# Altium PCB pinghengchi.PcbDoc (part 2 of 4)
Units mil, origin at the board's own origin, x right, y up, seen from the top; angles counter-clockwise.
Board outline 3880 x 3935 mil, 2 copper layers (Top Layer, Bottom Layer); 79 components, 147 nets, 520 pads, 52 vias.
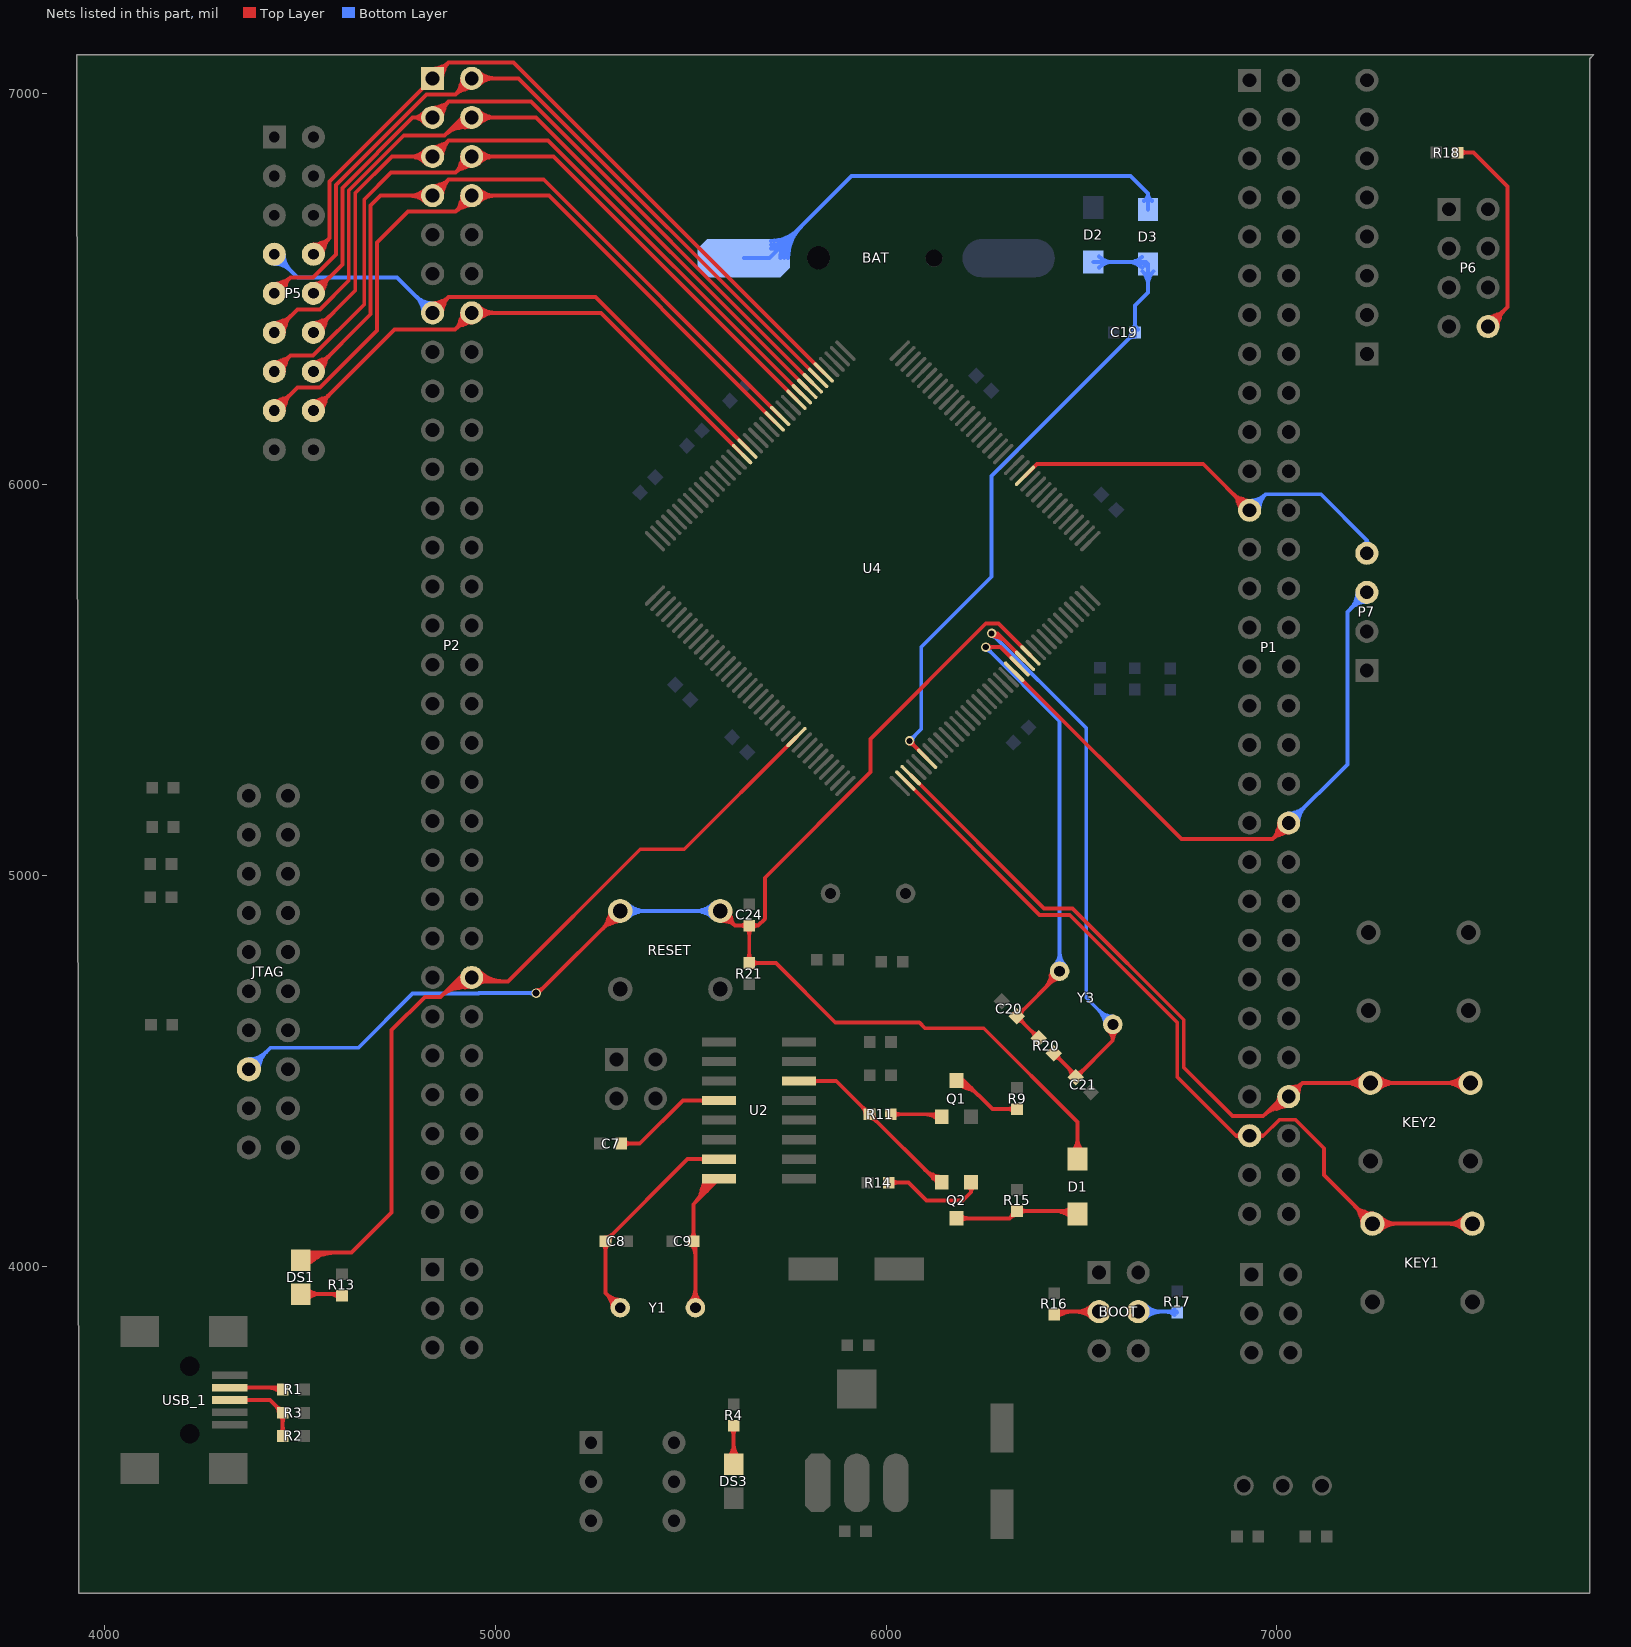
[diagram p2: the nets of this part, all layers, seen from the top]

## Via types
v1: diameter 24, hole 18, Top Layer to Bottom Layer, 42 vias
v2: diameter 24, hole 16, Top Layer to Bottom Layer, 4 vias
v3: diameter 125.98, hole 118.11, Top Layer to Bottom Layer, 4 vias
v4: diameter 30, hole 20, Top Layer to Bottom Layer, 2 vias

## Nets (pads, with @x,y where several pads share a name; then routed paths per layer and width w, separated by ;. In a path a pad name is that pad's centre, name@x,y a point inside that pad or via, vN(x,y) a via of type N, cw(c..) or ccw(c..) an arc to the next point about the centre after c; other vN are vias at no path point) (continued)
KEY1: KEY1.2 P1.55 U4.2 | length 3250.2
  Top Layer w10: U4.2@6049.15,5243.65 6392.81,4900 6470,4900 6745,4625 6745,4485 6895,4335 ; 7210.99,4136.5 ccw(c7251.76,4147.43) KEY1.2@7243.29,4106.08 ; 7217.59,4143.1 cw(c7206.67,4102.34) KEY1.2@7248.01,4110.8 ; KEY1.2@7500,4110 KEY1.2@7244.09,4110 7120,4234.09 7120,4303.02 7046.99,4376.03 7006.03,4376.03 6965,4335 ; 6895,4335 ccw(c6895,4347.71) 6906.94,4343.37 cw(c6895,4347.71) 6895,4335 ; 6895,4335 cw(c6895,4322.29) 6906.94,4326.63 ccw(c6895,4322.29) 6895,4335 ; 6895,4335 P1.55@6930,4335 6965,4335 ; 6965,4335 ccw(c6965,4322.29) 6953.06,4326.63 cw(c6965,4322.29) 6965,4335 ; 6965,4335 cw(c6965,4347.71) 6953.06,4343.37 ccw(c6965,4347.71) 6965,4335 ; 7199.71,4154.38 ccw(c7244.09,4198.77) 7244.09,4136 cw(c7244.09,4198.77) 7199.71,4154.38 ; 7199.71,4154.38 cw(c7155.32,4110) 7218.09,4110 ccw(c7155.32,4110) 7199.71,4154.38 ; 7216.78,4137.31 ccw(c7244.09,4164.63) 7244.09,4126 cw(c7244.09,4164.63) 7216.78,4137.31 ; 7216.78,4137.31 cw(c7189.47,4110) 7228.09,4110 ccw(c7189.47,4110) 7216.78,4137.31 ; 7282.72,4110 ccw(c7282.72,4071.37) 7255.41,4098.69 cw(c7282.72,4071.37) 7282.72,4110 ; 7282.72,4110 cw(c7282.72,4148.63) 7255.41,4121.31 ccw(c7282.72,4148.63) 7282.72,4110 ; 7306.86,4110 ccw(c7306.86,4047.23) 7262.48,4091.62 cw(c7306.86,4047.23) 7306.86,4110 ; 7306.86,4110 cw(c7306.86,4172.77) 7262.48,4128.38 ccw(c7306.86,4172.77) 7306.86,4110 ; 7437.23,4110 ccw(c7437.23,4172.77) 7481.62,4128.38 cw(c7437.23,4172.77) 7437.23,4110 ; 7437.23,4110 cw(c7437.23,4047.23) 7481.62,4091.62 ccw(c7437.23,4047.23) 7437.23,4110 ; 7461.37,4110 ccw(c7461.37,4148.63) 7488.69,4121.31 cw(c7461.37,4148.63) 7461.37,4110 ; 7461.37,4110 cw(c7461.37,4071.37) 7488.69,4098.69 ccw(c7461.37,4071.37) 7461.37,4110
KEY2: KEY2.2 P1.54 U4.3 | length 3539
  Top Layer w10: U4.3@6063.07,5257.57 6404.14,4916.5 6476.83,4916.5 6761.5,4631.83 6761.5,4510 6886.5,4385 6965,4385 ; 6999.06,4403.37 ccw(c6986.92,4454.87) P1.54@7034.97,4432.71 ; 7001.32,4419.49 cw(c7028.71,4412.15) P1.54@7030.31,4440.46 ; 7002.44,4414.09 ccw(c6995.17,4444.93) P1.54@7025.65,4436.24 ; P1.54@7017.76,4444.47 cw(c7052.2,4417.83) 7046.68,4461.01 ; P1.54@7039.47,4422.76 ccw(c7012.83,4457.2) 7056.01,4451.68 ; KEY2.2@7495,4470 KEY2.2@7239.09,4470 7065,4470 ; 6965,4385 cw(c7026.62,4323.39) 7029.26,4410.48 ccw(c7026.62,4323.39) 6965,4385 ; 6965,4385 7015,4435 P1.54@7030,4435 7065,4470 ; 7065,4470 ccw(c7091.64,4443.36) 7054.31,4438.3 cw(c7091.64,4443.36) 7065,4470 ; 7065,4470 cw(c7038.36,4496.64) 7033.3,4459.31 ccw(c7038.36,4496.64) 7065,4470 ; 7176.32,4470 ccw(c7176.32,4532.77) 7220.71,4488.38 cw(c7176.32,4532.77) 7176.32,4470 ; 7176.32,4470 cw(c7176.32,4407.23) 7220.71,4451.62 ccw(c7176.32,4407.23) 7176.32,4470 ; 7200.47,4470 ccw(c7200.47,4508.63) 7227.78,4481.31 cw(c7200.47,4508.63) 7200.47,4470 ; 7200.47,4470 cw(c7200.47,4431.37) 7227.78,4458.69 ccw(c7200.47,4431.37) 7200.47,4470 ; 7277.72,4470 ccw(c7277.72,4431.37) 7250.41,4458.69 cw(c7277.72,4431.37) 7277.72,4470 ; 7277.72,4470 cw(c7277.72,4508.63) 7250.41,4481.31 ccw(c7277.72,4508.63) 7277.72,4470 ; 7301.86,4470 ccw(c7301.86,4407.23) 7257.48,4451.62 cw(c7301.86,4407.23) 7301.86,4470 ; 7301.86,4470 cw(c7301.86,4532.77) 7257.48,4488.38 ccw(c7301.86,4532.77) 7301.86,4470 ; 7432.23,4470 ccw(c7432.23,4532.77) 7476.62,4488.38 cw(c7432.23,4532.77) 7432.23,4470 ; 7432.23,4470 cw(c7432.23,4407.23) 7476.62,4451.62 ccw(c7432.23,4407.23) 7432.23,4470 ; 7456.37,4470 ccw(c7456.37,4508.63) 7483.69,4481.31 cw(c7456.37,4508.63) 7456.37,4470 ; 7456.37,4470 cw(c7456.37,4431.37) 7483.69,4458.69 ccw(c7456.37,4431.37) 7456.37,4470 ; 6981.37,4401.37 cw(c7027.58,4355.16) 7029.56,4420.48 ccw(c7027.58,4355.16) 6981.37,4401.37 ; 6997.73,4417.73 cw(c7028.54,4386.92) 7029.86,4430.47 ccw(c7028.54,4386.92) 6997.73,4417.73 ; 6998.74,4418.74 ccw(c6982.47,4435) 7005.47,4435 cw(c6982.47,4435) 6998.74,4418.74
LED1: DS1.2 P2.48 U4.135 | length 3717.7
  Top Layer w10: DS1.2@4503.06,4017.04 4522.02,4036 4632,4036 4735,4139 4735,4605 4820,4690 4860,4690 ; DS1.2@4510.16,4026.64 ccw(c4521.8,4038.18) 4529.99,4023.99 ; DS1.2@4511.45,4025.04 ccw(c4527.96,4035.74) 4538.59,4019.19 ; DS1.2@4515.71,4035.1 ccw(c4522.66,4043.62) 4528.17,4034.09 ccw(c4533.67,4024.56) DS1.2@4522.81,4022.8 ; DS1.2@4517.26,4033.68 ccw(c4531.33,4047.64) 4541.23,4030.48 ; DS1.2@4519.85,4030.48 ccw(c4536.39,4041.2) 4547.04,4024.62 ; DS1.2@4522.38,4014.42 cw(c4537.17,4010.46) 4529.51,4023.72 ; 4530.14,4013.76 cw(c4519.53,4030.28) DS1.2@4503.06,4019.6 ; 4897.27,4720.54 ccw(c4890.01,4778.94) P2.48@4936.43,4742.78 ; 4899.28,4711.06 ccw(c4890.92,4778.22) P2.48@4944.32,4736.64 ; 4908.28,4731.65 ccw(c4905.46,4754.35) P2.48@4926.58,4745.57 ; 4923.23,4714.04 ccw(c4917.86,4757.24) P2.48@4952.21,4730.49 ; U4.135@5770.77,5355.01 5483.76,5068 5371.23,5068 5033.23,4730 4950,4730 P2.48@4940,4740 4910,4740 ; DS1.2@4503.06,4019.6 cw(c4542.66,3980) 4542.66,4036 ccw(c4542.66,3980) DS1.2@4503.06,4019.6 ; 4860,4690 cw(c4924.14,4625.86) 4936.62,4715.71 ccw(c4924.14,4625.86) 4860,4690 ; 4860,4690 4910,4740 ; 4910,4740 ccw(c4910,4746.08) 4915.96,4744.87 cw(c4910,4746.08) 4910,4740 ; 4910,4740 cw(c4910,4733.92) 4915.96,4735.13 ccw(c4910,4733.92) 4910,4740 ; 4975.07,4730 ccw(c4975.07,4704.93) 4957.34,4722.66 cw(c4975.07,4704.93) 4975.07,4730 ; 4975.07,4730 cw(c4975.07,4775.07) 4943.2,4743.2 ccw(c4975.07,4775.07) 4975.07,4730 ; DS1.2@4510.14,4012.53 cw(c4566.8,3955.86) 4566.8,4036 ccw(c4566.8,3955.86) DS1.2@4510.14,4012.53 ; DS1.2@4517.21,4005.46 cw(c4590.94,3931.72) 4590.94,4036 ccw(c4590.94,3931.72) DS1.2@4517.21,4005.46 ; 4874.21,4704.21 cw(c4927.61,4650.82) 4938,4725.61 ccw(c4927.61,4650.82) 4874.21,4704.21 ; 4888.42,4718.42 cw(c4931.07,4675.77) 4939.38,4735.52 ccw(c4931.07,4675.77) 4888.42,4718.42 ; 4902.63,4732.63 cw(c4934.54,4700.72) 4940.75,4745.42 ccw(c4934.54,4700.72) 4902.63,4732.63 ; P2.48@4950.27,4750.27 ccw(c4999.21,4799.21) 4999.21,4730 cw(c4999.21,4799.21) P2.48@4950.27,4750.27 ; P2.48@4957.34,4757.34 ccw(c5023.36,4823.36) 5023.36,4730 cw(c5023.36,4823.36) P2.48@4957.34,4757.34
NERST: C24.2 D1.1 JTAG.15 R21.1 RESET.1 U4.25 | length 6203.5
  Top Layer w10: v1(5105,4700) 5110,4700 RESET.1@5320,4910 ; 5286.9,4883.5 cw(c5327.66,4872.57) RESET.1@5319.2,4913.92 ; 5293.5,4876.9 ccw(c5282.57,4917.66) RESET.1@5323.92,4909.2 ; RESET.1@5560.91,4900.83 RESET.1@5560.91,4920 ; RESET.1@5564.51,4901.86 ccw(c5604.68,4930.55) 5598.02,4881.64 ; RESET.1@5575.91,4910 5613.41,4872.5 ; RESET.1@5584.04,4921.39 cw(c5555.36,4881.22) 5604.27,4887.89 ; U4.25@6369.3,5563.8 6288.1,5645 6255,5645 5960,5350 5960,5265 5690,4995 5690,4890 5672.5,4872.5 ; D1.1@6475,4290 D1.1@6490,4275 6490,4370 6250,4610 6100,4610 6085,4625 5870,4625 5718,4777 R21.1@5650,4777 5649.94,4777.06 C24.2@5649.94,4872.5 ; 5275.62,4865.62 ccw(c5231.23,4910) 5294,4910 cw(c5231.23,4910) 5275.62,4865.62 ; 5275.62,4865.62 cw(c5320,4821.23) 5320,4884 ccw(c5320,4821.23) 5275.62,4865.62 ; 5292.69,4882.69 ccw(c5265.37,4910) 5304,4910 cw(c5265.37,4910) 5292.69,4882.69 ; 5292.69,4882.69 cw(c5320,4855.37) 5320,4894 ccw(c5320,4855.37) 5292.69,4882.69 ; 5598.98,4886.92 ccw(c5581.11,4869.05) 5577.92,4894.13 cw(c5581.11,4869.05) 5598.98,4886.92 ; 5598.98,4886.92 cw(c5616.86,4904.8) 5591.78,4907.98 ccw(c5616.86,4904.8) 5598.98,4886.92 ; 5613.4,4872.5 ccw(c5584.36,4843.45) 5579.18,4884.21 cw(c5584.36,4843.45) 5613.4,4872.5 ; 5613.4,4872.5 cw(c5642.45,4901.55) 5601.7,4906.73 ccw(c5642.45,4901.55) 5613.4,4872.5 ; 5613.41,4872.5 C24.2@5649.94,4872.5 ; 5625.79,4872.5 ccw(c5625.79,4896.64) 5642.86,4879.57 cw(c5625.79,4896.64) 5625.79,4872.5 ; 5625.79,4872.5 cw(c5625.79,4848.36) C24.2@5642.86,4865.43 ; 5625.79,4872.5 cw(c5625.79,4848.36) C24.2@5642.86,4865.43 ; C24.2@5642.86,4865.43 cw(c5625.79,4848.36) 5649.94,4848.36 ; C24.2@5642.86,4865.43 cw(c5625.79,4848.36) 5649.94,4848.36 ; 5649.94,4848.36 cw(c5674.08,4848.36) 5657.01,4865.43 ccw(c5674.08,4848.36) 5649.94,4848.36 ; C24.2@5649.94,4872.5 5672.5,4872.5 ; R21.1@5657.07,4784.07 cw(c5674.3,4801.3) 5649.94,4801.3 ccw(c5674.3,4801.3) R21.1@5657.07,4784.07 ; R21.1@5657.07,4784.07 ccw(c5674.14,4801.14) 5674.14,4777 ; R21.1@5657.07,4784.07 ccw(c5674.14,4801.14) 5674.14,4777 ; 5672.5,4872.5 ccw(c5672.5,4852.05) 5657.34,4865.78 cw(c5672.5,4852.05) 5672.5,4872.5 ; 5672.5,4872.5 cw(c5672.5,4892.95) 5657.34,4879.22 ccw(c5672.5,4892.95) 5672.5,4872.5 ; 5674.14,4777 ccw(c5674.14,4752.86) 5657.07,4769.93 cw(c5674.14,4752.86) 5674.14,4777 ; 6490,4328.65 ccw(c6539.71,4328.65) 6504.56,4293.5 cw(c6539.71,4328.65) 6490,4328.65 ; 6490,4328.65 cw(c6440.29,4328.65) 6475.44,4293.5 ccw(c6440.29,4328.65) 6490,4328.65 ; v1@5105,4707 ccw(c5105,4735.97) 5125.49,4715.49 cw(c5105,4735.97) v1@5105,4707 ; R21.1@5642.93,4784.07 ccw(c5626.01,4800.99) 5649.94,4800.99 cw(c5626.01,4800.99) R21.1@5642.93,4784.07
  Bottom Layer w10: JTAG.15@4370,4505 4425,4560 4650,4560 4788.97,4698.97 4956.99,4698.97 4958.02,4700 v1(5105,4700) ; RESET.1@5320,4910 RESET.1@5575.91,4910 ; 4397.31,4532.31 ccw(c4424.63,4505) 4386,4505 cw(c4424.63,4505) 4397.31,4532.31 ; 4397.31,4532.31 cw(c4370,4559.63) 4370,4521 ccw(c4370,4559.63) 4397.31,4532.31 ; 4414.38,4549.38 ccw(c4458.77,4505) 4396,4505 cw(c4458.77,4505) 4414.38,4549.38 ; 4414.38,4549.38 cw(c4370,4593.77) 4370,4531 ccw(c4370,4593.77) 4414.38,4549.38 ; 5088.1,4700 ccw(c5088.1,4716.9) 5100.05,4704.95 cw(c5088.1,4716.9) 5088.1,4700 ; 5088.1,4700 cw(c5088.1,4683.1) 5100.05,4695.05 ccw(c5088.1,4683.1) 5088.1,4700 ; 5358.63,4910 ccw(c5358.63,4871.37) 5331.31,4898.69 cw(c5358.63,4871.37) 5358.63,4910 ; 5358.63,4910 cw(c5358.63,4948.63) 5331.31,4921.31 ccw(c5358.63,4948.63) 5358.63,4910 ; 5382.77,4910 ccw(c5382.77,4847.23) 5338.38,4891.62 cw(c5382.77,4847.23) 5382.77,4910 ; 5382.77,4910 cw(c5382.77,4972.77) 5338.38,4928.38 ccw(c5382.77,4972.77) 5382.77,4910 ; 5513.14,4910 ccw(c5513.14,4972.77) 5557.52,4928.38 cw(c5513.14,4972.77) 5513.14,4910 ; 5513.14,4910 cw(c5513.14,4847.23) 5557.52,4891.62 ccw(c5513.14,4847.23) 5513.14,4910 ; 5537.28,4910 ccw(c5537.28,4948.63) 5564.59,4921.31 cw(c5537.28,4948.63) 5537.28,4910 ; 5537.28,4910 cw(c5537.28,4871.37) 5564.59,4898.69 ccw(c5537.28,4871.37) 5537.28,4910
NetBAT_1: BAT.1 D3.1 | length 2046.1
  Bottom Layer w10: BAT.1@5636.35,6580 5702,6580 5912,6790 6625,6790 6670,6745 ; D3.1@6670,6705 6670,6745 ; 6670,6745 ccw(c6691.28,6745) 6680.47,6726.67 cw(c6691.28,6745) 6670,6745 ; 6670,6745 cw(c6648.72,6745) 6659.53,6726.67 ccw(c6648.72,6745) 6670,6745 ; BAT.1@5705.25,6604.21 ccw(c5705.25,6654.82) 5741.03,6619.03 cw(c5705.25,6654.82) BAT.1@5705.25,6604.21 ; BAT.1@5705.25,6614.21 ccw(c5705.25,6688.96) 5758.11,6636.11 cw(c5705.25,6688.96) BAT.1@5705.25,6614.21 ; BAT.1@5705.25,6624.21 ccw(c5705.25,6723.1) 5775.18,6653.18 cw(c5705.25,6723.1) BAT.1@5705.25,6624.21 ; BAT.1@5729.46,6580 cw(c5795.77,6580) 5748.88,6626.88 ccw(c5795.77,6580) BAT.1@5729.46,6580 ; BAT.1@5739.46,6580 cw(c5829.91,6580) 5765.96,6643.96 ccw(c5829.91,6580) BAT.1@5739.46,6580 ; BAT.1@5749.46,6580 cw(c5864.05,6580) 5783.03,6661.03 ccw(c5864.05,6580) BAT.1@5749.46,6580
NetBOOT_3: BOOT.3 R16.2 | length 551.3
  Top Layer w10: R16.2@6437.78,3883.71 ccw(c6447.97,3891.78) 6454.48,3880.52 ; BOOT.3@6545,3885 6437.44,3885 R16.2@6429.94,3877.5 ; R16.2@6429.94,3877.5 cw(c6448.04,3859.39) 6448.04,3885 ccw(c6448.04,3859.39) R16.2@6429.94,3877.5 ; 6485.79,3885 ccw(c6485.79,3944.21) 6527.66,3902.34 cw(c6485.79,3944.21) 6485.79,3885 ; 6485.79,3885 cw(c6485.79,3825.79) 6527.66,3867.66 ccw(c6485.79,3825.79) 6485.79,3885 ; 6509.93,3885 ccw(c6509.93,3920.07) 6534.73,3895.27 cw(c6509.93,3920.07) 6509.93,3885 ; 6509.93,3885 cw(c6509.93,3849.93) 6534.73,3874.73 ccw(c6509.93,3849.93) 6509.93,3885 ; R16.2@6437.01,3870.43 cw(c6472.18,3835.25) 6472.18,3885 ccw(c6472.18,3835.25) R16.2@6437.01,3870.43
NetBOOT_4: BOOT.4 R17.1 | length 472.9
  Bottom Layer w10: BOOT.4@6645,3885 6743,3885 R17.1@6745,3883 ; 6680.07,3885 ccw(c6680.07,3849.93) 6655.27,3874.73 cw(c6680.07,3849.93) 6680.07,3885 ; 6680.07,3885 cw(c6680.07,3920.07) 6655.27,3895.27 ccw(c6680.07,3920.07) 6680.07,3885 ; 6704.21,3885 ccw(c6704.21,3825.79) 6662.34,3867.66 cw(c6704.21,3825.79) 6704.21,3885 ; 6704.21,3885 cw(c6704.21,3944.21) 6662.34,3902.34 ccw(c6704.21,3944.21) 6704.21,3885 ; 6716.03,3885 cw(c6716.03,3854.03) 6737.93,3875.93 ccw(c6716.03,3854.03) 6716.03,3885 ; 6725.69,3885 ccw(c6725.69,3902.31) 6737.93,3890.07 cw(c6725.69,3902.31) 6725.69,3885
NetC7_2: C7.2 U2.4 | length 423.2
  Top Layer w10: C7.2@5322.5,4314.94 5369.94,4314.94 5480,4425 U2.4@5572.64,4425 ; 5346.64,4314.94 ccw(c5346.64,4290.79) 5329.57,4307.86 cw(c5346.64,4290.79) 5346.64,4314.94 ; 5346.64,4314.94 cw(c5346.64,4339.08) 5329.57,4322.01 ccw(c5346.64,4339.08) 5346.64,4314.94 ; 5524.7,4425 ccw(c5524.7,4441.44) 5536.33,4429.82 cw(c5524.7,4441.44) 5524.7,4425 ; 5524.7,4425 cw(c5524.7,4408.56) 5536.33,4420.18 ccw(c5524.7,4408.56) 5524.7,4425
NetC8_2: C8.2 U2.7 Y1.1 | length 995.1
  Top Layer w10: 5293.25,3920.2 ccw(c5327.01,3929.24) Y1.1@5320,3895 ; 5294.8,3921.75 cw(c5285.76,3887.99) Y1.1@5320,3895 ; U2.7@5572.64,4275 5492.44,4275 C8.2@5282.5,4065.06 5282.5,3932.5 Y1.1@5320,3895 ; 5282.5,4040.92 ccw(c5258.36,4040.92) 5275.43,4057.99 cw(c5258.36,4040.92) 5282.5,4040.92 ; 5282.5,4040.92 cw(c5306.64,4040.92) 5289.57,4057.99 ccw(c5306.64,4040.92) 5282.5,4040.92 ; 5285.86,3929.14 ccw(c5320,3963.28) 5320,3915 cw(c5320,3963.28) 5285.86,3929.14 ; 5285.86,3929.14 cw(c5251.72,3895) 5300,3895 ccw(c5251.72,3895) 5285.86,3929.14 ; 5299.57,4082.14 ccw(c5316.64,4065.06) 5292.5,4065.06 cw(c5316.64,4065.06) 5299.57,4082.14 ; 5299.57,4082.14 cw(c5282.5,4099.21) 5282.5,4075.06 ccw(c5282.5,4099.21) 5299.57,4082.14 ; 5524.7,4275 ccw(c5524.7,4291.44) 5536.33,4279.82 cw(c5524.7,4291.44) 5524.7,4275 ; 5524.7,4275 cw(c5524.7,4258.56) 5536.33,4270.18 ccw(c5524.7,4258.56) 5524.7,4275
NetC9_2: C9.2 U2.8 Y1.2 | length 1053.6
  Top Layer w10: Y1.2@5512.13,3895 5512.13,4060.31 C9.2@5507.5,4064.94 5507.5,4159.86 ; 5527.39,4194.87 cw(c5565.48,4186.09) U2.8@5544.75,4219.23 ; U2.8@5535.26,4221.57 cw(c5511.96,4208.01) 5538.03,4201.13 ; U2.8@5572.64,4225 5507.5,4159.86 ; 5507.5,4089.08 ccw(c5531.64,4089.08) 5514.57,4072.01 cw(c5531.64,4089.08) 5507.5,4089.08 ; 5507.5,4089.08 cw(c5483.36,4089.08) 5500.43,4072.01 ccw(c5483.36,4089.08) 5507.5,4089.08 ; 5507.5,4159.86 ccw(c5442.73,4224.64) 5534.33,4224.97 cw(c5442.73,4224.64) 5507.5,4159.86 ; 5512.13,3943.28 ccw(c5560.41,3943.28) 5526.27,3909.14 cw(c5560.41,3943.28) 5512.13,3943.28 ; 5512.13,3943.28 cw(c5463.84,3943.28) 5497.98,3909.14 ccw(c5463.84,3943.28) 5512.13,3943.28 ; C9.2@5500.43,4057.86 cw(c5472.19,4029.63) 5512.13,4029.63 ccw(c5472.19,4029.63) C9.2@5500.43,4057.86 ; 5524.48,4176.85 ccw(c5476.57,4224.76) 5544.33,4225.01 cw(c5476.57,4224.76) 5524.48,4176.85 ; 5541.47,4193.83 ccw(c5510.41,4224.89) 5554.33,4225.05 cw(c5510.41,4224.89) 5541.47,4193.83 ; 5558.45,4210.81 ccw(c5544.25,4225.01) 5564.33,4225.09 cw(c5544.25,4225.01) 5558.45,4210.81
NetC19_1: C19.1 D2.2 D3.2 U4.6 | length 2451.2
  Top Layer w10: v2(6060,5345) 6104.83,5300.17 U4.6@6104.83,5299.33 ; 6071.95,5333.05 ccw(c6060,5321.1) 6060,5338 cw(c6060,5321.1) 6071.95,5333.05 ; 6071.95,5333.05 cw(c6083.9,5345) 6067,5345 ccw(c6083.9,5345) 6071.95,5333.05
  Bottom Layer w10: v2(6060,5345) 6090,5375 6090,5585 6270,5765 6270,6023 C19.1@6637,6390 6637,6459 6670,6492 D3.2@6670,6565 6665,6570 D2.2@6530,6570 ; 6071.95,5356.95 ccw(c6083.9,5345) 6067,5345 cw(c6083.9,5345) 6071.95,5356.95 ; 6071.95,5356.95 cw(c6060,5368.9) 6060,5352 ccw(c6060,5368.9) 6071.95,5356.95 ; 6579.71,6570 ccw(c6579.71,6520.29) 6544.56,6555.44 cw(c6579.71,6520.29) 6579.71,6570 ; 6579.71,6570 cw(c6579.71,6619.71) 6544.56,6584.56 ccw(c6579.71,6619.71) 6579.71,6570 ; 6619.93,6372.93 ccw(c6602.86,6390) 6627,6390 cw(c6602.86,6390) 6619.93,6372.93 ; 6619.93,6372.93 cw(c6637,6355.86) 6637,6380 ccw(c6637,6355.86) 6619.93,6372.93 ; 6637,6414.14 ccw(c6661.14,6414.14) 6644.07,6397.07 cw(c6661.14,6414.14) 6637,6414.14 ; 6637,6414.14 cw(c6612.86,6414.14) 6629.93,6397.07 ccw(c6612.86,6414.14) 6637,6414.14 ; 6670,6511.35 ccw(c6620.29,6511.35) 6655.44,6546.5 cw(c6620.29,6511.35) 6670,6511.35 ; 6670,6511.35 cw(c6719.71,6511.35) 6684.56,6546.5 ccw(c6719.71,6511.35) 6670,6511.35 ; 6617.72,6570 cw(c6617.72,6516.66) 6655.44,6554.38 ccw(c6617.72,6516.66) 6617.72,6570 ; 6622.86,6570 ccw(c6622.86,6616.08) 6655.44,6583.5 cw(c6622.86,6616.08) 6622.86,6570 ; 6641.87,6570 cw(c6641.87,6540.8) 6662.51,6561.45 ccw(c6641.87,6540.8) 6641.87,6570
NetC20_2: C20.2 R20.2 U4.23 Y3.2 | length 2174.5
  Top Layer w10: v2(6255,5585) 6292.42,5585 U4.23@6341.46,5535.96 ; 6347,4627.13 cw(c6351.52,4644.02) C20.2@6334.4,4640.51 ; 6347,4653.89 ccw(c6351.52,4637) C20.2@6334.4,4640.51 ; 6347.78,4627.91 ccw(c6330.89,4623.39) C20.2@6334.4,4640.51 ; 6347.78,4653.11 cw(c6330.89,4657.63) C20.2@6334.4,4640.51 ; 6377.25,4596.98 ccw(c6393.96,4601.46) R20.2@6390.6,4584.49 ; 6377.89,4597.9 cw(c6373.32,4580.84) R20.2@6390.6,4584.49 ; 6416.51,4727.34 cw(c6455.94,4716.77) Y3.2@6444.15,4755.85 ; 6421.15,4744.69 cw(c6449.83,4737) Y3.2@6441.26,4765.43 ; 6422.27,4729.99 ccw(c6414.58,4758.68) Y3.2@6444.15,4755.85 ; 6271.9,5585 ccw(c6271.9,5568.1) 6259.95,5580.05 cw(c6271.9,5568.1) 6271.9,5585 ; 6271.9,5585 cw(c6271.9,5601.9) 6259.95,5589.95 ccw(c6271.9,5601.9) 6271.9,5585 ; C20.2@6334.4,4640.51 6390.42,4584.49 R20.2@6390.6,4584.49 ; C20.2@6334.4,4640.51 6444.15,4750.26 Y3.2@6444.15,4755.85 ; C20.2@6344.4,4640.51 ccw(c6368.54,4640.51) 6351.47,4623.44 ; C20.2@6344.4,4640.51 cw(c6368.54,4640.51) 6351.47,4657.58 ; C20.2@6344.4,4640.51 ccw(c6368.54,4640.51) 6351.47,4623.44 ; C20.2@6344.4,4640.51 cw(c6368.54,4640.51) 6351.47,4657.58 ; 6351.47,4623.44 ccw(c6334.4,4606.37) 6334.4,4630.51 cw(c6334.4,4606.37) 6351.47,4623.44 ; 6351.47,4657.58 cw(c6334.4,4674.65) 6334.4,4650.51 ccw(c6334.4,4674.65) 6351.47,4657.58 ; 6373.22,4601.69 ccw(c6390.6,4619.07) 6390.6,4594.49 cw(c6390.6,4619.07) 6373.22,4601.69 ; 6373.66,4601.25 cw(c6356.89,4584.49) 6380.6,4584.49 ccw(c6356.89,4584.49) 6373.66,4601.25 ; 6406.05,4712.15 ccw(c6362.35,4755.85) 6424.15,4755.85 cw(c6362.35,4755.85) 6406.05,4712.15 ; 6419.56,4725.67 cw(c6444.15,4701.08) 6444.15,4735.85 ccw(c6444.15,4701.08) 6419.56,4725.67 ; 6423.12,4729.23 ccw(c6396.49,4755.85) 6434.15,4755.85 cw(c6396.49,4755.85) 6423.12,4729.23
  Bottom Layer w10: v2(6255,5585) 6444.15,5395.85 Y3.2@6444.15,4755.85 ; 6266.95,5573.05 ccw(c6255,5561.1) 6255,5578 cw(c6255,5561.1) 6266.95,5573.05 ; 6266.95,5573.05 cw(c6278.9,5585) 6262,5585 ccw(c6278.9,5585) 6266.95,5573.05 ; 6444.15,4804.14 ccw(c6492.43,4804.14) 6458.29,4770 cw(c6492.43,4804.14) 6444.15,4804.14 ; 6444.15,4804.14 cw(c6395.86,4804.14) 6430,4770 ccw(c6395.86,4804.14) 6444.15,4804.14
NetC21_2: C21.2 R20.1 U4.24 Y3.1 | length 2297.7
  Top Layer w10: v2@6276.06,5623.5 ccw(c6310.69,5643.49) 6300.34,5604.87 ; 6285.26,5620 U4.24@6355.38,5549.88 ; 6441.69,4532.53 cw(c6446.21,4549.41) R20.1@6429.09,4545.91 ; 6442.47,4533.31 ccw(c6425.59,4528.79) R20.1@6429.09,4545.91 ; 6471.44,4500 ccw(c6493.49,4505.91) C21.2@6485.6,4484.49 ; 6498.2,4497.87 ccw(c6502.72,4480.98) C21.2@6485.6,4484.49 ; 6498.98,4497.09 cw(c6482.09,4501.61) C21.2@6485.6,4484.49 ; Y3.1@6580,4620 6580,4578.89 ; R20.1@6429.09,4545.91 6485.6,4489.4 C21.2@6485.6,4484.49 ; 6446.16,4528.84 ccw(c6429.09,4511.77) 6429.09,4535.91 cw(c6429.09,4511.77) 6446.16,4528.84 ; 6446.16,4528.84 cw(c6463.23,4545.91) 6439.09,4545.91 ccw(c6463.23,4545.91) 6446.16,4528.84 ; C21.2@6485.6,4484.49 6580,4578.89 ; C21.2@6485.6,4494.49 ccw(c6485.6,4518.63) 6502.67,4501.56 ; C21.2@6485.6,4494.49 cw(c6485.6,4506.78) 6476.91,4498.09 ccw(c6485.6,4506.78) C21.2@6485.6,4494.49 ; C21.2@6485.6,4494.49 ccw(c6485.6,4518.63) 6502.67,4501.56 ; 6502.67,4501.56 ccw(c6519.74,4484.49) 6495.6,4484.49 cw(c6519.74,4484.49) 6502.67,4501.56 ; 6580,4578.89 ccw(c6547.76,4578.89) 6567.66,4604.26 cw(c6547.76,4578.89) 6580,4578.89 ; 6580,4578.89 cw(c6612.24,4578.89) 6592.34,4604.26 ccw(c6612.24,4578.89) 6580,4578.89 ; v2@6270,5613 cw(c6270,5559.26) 6308,5597.26 ccw(c6270,5559.26) v2@6270,5613 ; v2@6270,5623 cw(c6270,5593.4) 6290.93,5614.33 ccw(c6270,5593.4) v2@6270,5623 ; 6465.06,4509.94 cw(c6439.61,4484.49) 6475.6,4484.49 ccw(c6439.61,4484.49) 6465.06,4509.94
  Bottom Layer w10: v2(6270,5620) 6512,5378 6512,4688 Y3.1@6580,4620 ; 6281.95,5608.05 ccw(c6270,5596.1) 6270,5613 cw(c6270,5596.1) 6281.95,5608.05 ; 6281.95,5608.05 cw(c6293.9,5620) 6277,5620 ccw(c6293.9,5620) 6281.95,5608.05 ; 6545.86,4654.14 ccw(c6580,4688.28) 6580,4640 cw(c6580,4688.28) 6545.86,4654.14 ; 6545.86,4654.14 cw(c6511.72,4620) 6560,4620 ccw(c6511.72,4620) 6545.86,4654.14
NetD1_2: D1.2 Q2.3 R15.2 | length 784.5
  Top Layer w10: Q2.3@6180,4123.74 6316.18,4123.74 R15.2@6334.94,4142.5 6482.5,4142.5 D1.2@6490,4135 ; 6210.7,4123.74 ccw(c6210.7,4093.04) 6188.99,4114.75 cw(c6210.7,4093.04) 6210.7,4123.74 ; 6210.7,4123.74 cw(c6210.7,4154.44) 6188.99,4132.73 ccw(c6210.7,4154.44) 6210.7,4123.74 ; 6317.86,4125.43 ccw(c6300.79,4142.5) 6324.94,4142.5 cw(c6300.79,4142.5) 6317.86,4125.43 ; 6317.86,4125.43 cw(c6334.94,4108.36) 6334.94,4132.5 ccw(c6334.94,4108.36) 6317.86,4125.43 ; 6359.08,4142.5 ccw(c6359.08,4118.36) 6342.01,4135.43 cw(c6359.08,4118.36) 6359.08,4142.5 ; 6359.08,4142.5 cw(c6359.08,4166.64) 6342.01,4149.57 ccw(c6359.08,4166.64) 6359.08,4142.5 ; 6431.69,4142.5 cw(c6431.69,4080.63) 6475.44,4124.38 ccw(c6431.69,4080.63) 6431.69,4142.5 ; 6448.89,4142.5 ccw(c6448.89,4180.05) 6475.44,4153.5 cw(c6448.89,4180.05) 6448.89,4142.5 ; 6455.83,4142.5 cw(c6455.83,4104.77) 6482.51,4131.45 ccw(c6455.83,4104.77) 6455.83,4142.5
NetDS1_1: DS1.1 R13.1 | length 317.8
  Top Layer w10: DS1.1@4503.06,3930.03 4603.97,3930.03 R13.1@4608,3926 ; 4551.35,3930.03 ccw(c4551.35,3881.75) 4517.21,3915.89 cw(c4551.35,3881.75) 4551.35,3930.03 ; 4551.35,3930.03 cw(c4551.35,3978.32) 4517.21,3944.17 ccw(c4551.35,3978.32) 4551.35,3930.03 ; 4574.12,3930.03 cw(c4574.12,3892.12) 4600.93,3918.93 ccw(c4574.12,3892.12) 4574.12,3930.03
NetDS3_1: DS3.1 R4.1 | length 325.6
  Top Layer w10: DS3.1@5609.94,3494.97 5610,3495.03 R4.1@5610,3593 ; 5610,3568.86 ccw(c5585.86,3568.86) 5602.93,3585.93 cw(c5585.86,3568.86) 5610,3568.86 ; 5610,3568.86 cw(c5634.14,3568.86) 5617.07,3585.93 ccw(c5634.14,3568.86) 5610,3568.86 ; DS3.1@5595.79,3511.67 ccw(c5561.5,3545.97) 5610,3545.97 cw(c5561.5,3545.97) DS3.1@5595.79,3511.67 ; 5610,3545.66 ccw(c5658.07,3545.66) 5624.08,3511.67 cw(c5658.07,3545.66) 5610,3545.66
NetP6_8: P6.8 R18.1 | length 999.9
  Top Layer w10: R18.1@7462,6850 7503,6850 7590,6763 7590,6455 P6.8@7540,6405 ; P6.8@7534.64,6406.1 cw(c7572.3,6398.39) 7562.35,6435.52 ; P6.8@7541.1,6399.64 ccw(c7533.39,6437.3) 7570.52,6427.35 ; 7486.14,6850 ccw(c7486.14,6825.86) 7469.07,6842.93 cw(c7486.14,6825.86) 7486.14,6850 ; 7486.14,6850 cw(c7486.14,6874.14) 7469.07,6857.07 ccw(c7486.14,6874.14) 7486.14,6850 ; 7564.8,6429.8 ccw(c7589.6,6405) 7554.53,6405 cw(c7589.6,6405) 7564.8,6429.8 ; 7564.8,6429.8 cw(c7540,6454.6) 7540,6419.53 ccw(c7540,6454.6) 7564.8,6429.8 ; 7581.87,6446.87 ccw(c7623.74,6405) 7564.53,6405 cw(c7623.74,6405) 7581.87,6446.87 ; 7581.87,6446.87 cw(c7540,6488.74) 7540,6429.53 ccw(c7540,6488.74) 7581.87,6446.87
NetQ1_2: Q1.2 R11.1 | length 344.1
  Top Layer w10: R11.1@6012,4390 6136.34,4390 Q1.2@6142.6,4383.74 ; 6036.14,4390 ccw(c6036.14,4365.86) 6019.07,4382.93 cw(c6036.14,4365.86) 6036.14,4390 ; 6036.14,4390 cw(c6036.14,4414.14) 6019.07,4397.07 ccw(c6036.14,4414.14) 6036.14,4390 ; 6099.16,4390 cw(c6099.16,4341.29) 6133.61,4375.73 ccw(c6099.16,4341.29) 6099.16,4390 ; 6123.3,4390 cw(c6123.3,4365.43) 6140.68,4382.8 ccw(c6123.3,4365.43) 6123.3,4390 ; 6124.63,4390 ccw(c6124.63,4402.69) 6133.61,4393.72 cw(c6124.63,4402.69) 6124.63,4390
NetQ1_3: Q1.3 R9.1 | length 634
  Top Layer w10: Q1.3@6180,4476.26 6198.74,4476.26 ; Q1.3@6182.35,4476.63 ccw(c6224.35,4500.88) 6211.8,4454.04 ; Q1.3@6186.36,4464.26 cw(c6197.23,4445.43) 6202.86,4466.43 ; Q1.3@6191.48,4480.75 ccw(c6219.52,4494.14) 6211.48,4464.12 ; R9.1@6335,4403 6272,4403 6198.74,4476.26 ; 6198.74,4476.26 ccw(c6198.74,4468.81) 6191.82,4471.56 cw(c6198.74,4468.81) 6198.74,4476.26 ; 6198.74,4476.26 cw(c6198.74,4483.71) 6191.82,4480.96 ccw(c6198.74,4483.71) 6198.74,4476.26 ; 6310.86,4403 ccw(c6310.86,4427.14) 6327.93,4410.07 cw(c6310.86,4427.14) 6310.86,4403 ; 6310.86,4403 cw(c6310.86,4378.86) 6327.93,4395.93 ccw(c6310.86,4378.86) 6310.86,4403 ; Q1.3@6180,4462.56 cw(c6180,4384.24) 6235.38,4439.62 ccw(c6180,4384.24) Q1.3@6180,4462.56 ; Q1.3@6180,4472.56 cw(c6180,4418.38) 6218.31,4456.69 ccw(c6180,4418.38) Q1.3@6180,4472.56 ; Q1.3@6180,4482.56 cw(c6180,4452.52) 6201.24,4473.76 ccw(c6180,4452.52) Q1.3@6180,4482.56
NetQ2_1: Q2.1 R11.2 U2.14 | length 895.1
  Top Layer w10: U2.14@5777.36,4475 5872.56,4475 R11.2@5957.5,4390.06 6131.3,4216.26 Q2.1@6142.6,4216.26 ; 6113.44,4237.77 cw(c6102.53,4197.06) Q2.1@6140.17,4216.02 ; Q2.1@6130.07,4215.08 ccw(c6116.56,4212.75) 6120.11,4225.99 ccw(c6125.5,4246.11) Q2.1@6136.12,4228.19 ; 5825.3,4475 ccw(c5825.3,4458.56) 5813.67,4470.18 cw(c5825.3,4458.56) 5825.3,4475 ; 5825.3,4475 cw(c5825.3,4491.44) 5813.67,4479.82 ccw(c5825.3,4491.44) 5825.3,4475 ; 5940.43,4407.14 ccw(c5957.5,4424.21) 5957.5,4400.06 cw(c5957.5,4424.21) 5940.43,4407.14 ; 5940.43,4407.14 cw(c5923.36,4390.06) 5947.5,4390.06 ccw(c5923.36,4390.06) 5940.43,4407.14 ; 5974.57,4372.99 ccw(c5957.5,4355.92) 5957.5,4380.06 cw(c5957.5,4355.92) 5974.57,4372.99 ; 5974.57,4372.99 cw(c5991.64,4390.06) 5967.5,4390.06 ccw(c5991.64,4390.06) 5974.57,4372.99 ; 6099.93,4247.64 ccw(c6142.6,4290.3) 6142.6,4229.96 cw(c6142.6,4290.3) 6099.93,4247.64 ; 6117,4230.56 ccw(c6142.6,4256.16) 6142.6,4219.96 cw(c6142.6,4256.16) 6117,4230.56
NetQ2_2: Q2.2 R14.1 | length 408
  Top Layer w10: R14.1@6007,4215 6057,4215 6103,4169 6196,4169 6217.4,4190.4 ; Q2.2@6217.4,4216.26 6217.4,4190.4 ; 6031.14,4215 ccw(c6031.14,4190.86) 6014.07,4207.93 cw(c6031.14,4190.86) 6031.14,4215 ; 6031.14,4215 cw(c6031.14,4239.14) 6014.07,4222.07 ccw(c6031.14,4239.14) 6031.14,4215 ; 6217.4,4190.4 ccw(c6199.44,4190.4) 6209.96,4204.97 cw(c6199.44,4190.4) 6217.4,4190.4 ; 6217.4,4190.4 cw(c6235.37,4190.4) 6224.85,4204.97 ccw(c6235.37,4190.4) 6217.4,4190.4
NetR1_2: R1.2 USB_1.2 | length 229.4
  Top Layer w10: USB_1.2@4321.06,3690.5 R1.2@4452.07,3690.5 ; 4368.18,3690.5 ccw(c4368.18,3678.81) 4359.91,3687.07 cw(c4368.18,3678.81) 4368.18,3690.5 ; 4368.18,3690.5 cw(c4368.18,3702.19) 4359.91,3693.92 ccw(c4368.18,3702.19) 4368.18,3690.5 ; 4421.65,3690.5 cw(c4421.65,3651.22) 4449.43,3678.99 ccw(c4421.65,3651.22) 4421.65,3690.5
NetR2_2: R2.2 R3.2 USB_1.3 | length 472.3
  Top Layer w10: USB_1.3@4321.06,3659 4423.56,3659 R3.2@4456.5,3626.06 R2.2@4456.5,3567.06 ; 4368.18,3659 ccw(c4368.18,3647.31) 4359.91,3655.58 cw(c4368.18,3647.31) 4368.18,3659 ; 4368.18,3659 cw(c4368.18,3670.69) 4359.91,3662.43 ccw(c4368.18,3670.69) 4368.18,3659 ; 4439.43,3643.14 ccw(c4456.5,3660.21) 4456.5,3636.06 cw(c4456.5,3660.21) 4439.43,3643.14 ; 4439.43,3643.14 cw(c4422.36,3626.06) 4446.5,3626.06 ccw(c4422.36,3626.06) 4439.43,3643.14 ; 4456.5,3591.21 ccw(c4480.64,3591.21) 4463.57,3574.14 cw(c4480.64,3591.21) 4456.5,3591.21 ; 4456.5,3591.21 cw(c4432.36,3591.21) 4449.43,3574.14 ccw(c4432.36,3591.21) 4456.5,3591.21 ; 4456.5,3601.92 ccw(c4432.36,3601.92) 4449.43,3618.99 cw(c4432.36,3601.92) 4456.5,3601.92 ; 4456.5,3601.92 cw(c4480.64,3601.92) 4463.57,3618.99 ccw(c4480.64,3601.92) 4456.5,3601.92
OLED_SCL: P1.40 P7.3 U4.22 | length 2534.9
  Top Layer w10: U4.22@6327.54,5522.04 6755.61,5093.97 6988.97,5093.97 ; 6999.68,5111.69 cw(c7037.8,5102.07) P1.40@7028.74,5140.33 ; 7006.69,5104.68 ccw(c6997.07,5142.8) P1.40@7035.33,5133.74 ; P1.40@7030,5135 6988.97,5093.97 ; 6988.97,5093.97 ccw(c6949.13,5133.82) 7005.48,5134.64 cw(c6949.13,5133.82) 6988.97,5093.97 ; 6988.97,5093.97 cw(c7028.82,5054.13) 7029.64,5110.48 ccw(c7028.82,5054.13) 6988.97,5093.97 ; 7005.7,5110.7 ccw(c6982.1,5134.3) 7015.47,5134.79 cw(c6982.1,5134.3) 7005.7,5110.7 ; 7005.7,5110.7 cw(c7029.3,5087.1) 7029.79,5120.47 ccw(c7029.3,5087.1) 7005.7,5110.7
  Bottom Layer w10: P1.40@7030,5135 7180,5285 7180,5675 P7.3@7230,5725 ; 7054.8,5159.8 ccw(c7079.6,5135) 7044.53,5135 cw(c7079.6,5135) 7054.8,5159.8 ; 7054.8,5159.8 cw(c7030,5184.6) 7030,5149.53 ccw(c7030,5184.6) 7054.8,5159.8 ; 7071.87,5176.87 ccw(c7113.74,5135) 7054.53,5135 cw(c7113.74,5135) 7071.87,5176.87 ; 7071.87,5176.87 cw(c7030,5218.74) 7030,5159.53 ccw(c7030,5218.74) 7071.87,5176.87 ; 7188.13,5683.13 ccw(c7146.26,5725) 7205.47,5725 cw(c7146.26,5725) 7188.13,5683.13 ; 7188.13,5683.13 cw(c7230,5641.26) 7230,5700.47 ccw(c7230,5641.26) 7188.13,5683.13 ; 7205.2,5700.2 ccw(c7180.4,5725) 7215.47,5725 cw(c7180.4,5725) 7205.2,5700.2 ; 7205.2,5700.2 cw(c7230,5675.4) 7230,5710.47 ccw(c7230,5675.4) 7205.2,5700.2
OLED_SDA: P1.23 P7.4 U4.49 | length 1756
  Top Layer w10: U4.49@6355.38,6023.14 6385.83,6053.58 6811.42,6053.58 P1.23@6930,5935 ; 6899.48,5957.35 ccw(c6936.61,5967.3) P1.23@6928.9,5929.64 ; 6907.65,5965.52 cw(c6897.7,5928.39) P1.23@6935.36,5936.1 ; 6888.13,5976.87 ccw(c6930,6018.74) 6930,5959.53 cw(c6930,6018.74) 6888.13,5976.87 ; 6888.13,5976.87 cw(c6846.26,5935) 6905.47,5935 ccw(c6846.26,5935) 6888.13,5976.87 ; 6905.2,5959.8 ccw(c6930,5984.6) 6930,5949.53 cw(c6930,5984.6) 6905.2,5959.8 ; 6905.2,5959.8 cw(c6880.4,5935) 6915.47,5935 ccw(c6880.4,5935) 6905.2,5959.8
  Bottom Layer w10: P1.23@6930,5935 6971.03,5976.03 ; P7.4@7230,5825 7230,5858.23 ; 6954.3,5959.3 ccw(c6977.9,5935.7) 6944.53,5935.21 cw(c6977.9,5935.7) 6954.3,5959.3 ; 6954.3,5959.3 cw(c6930.7,5982.9) 6930.21,5949.53 ccw(c6930.7,5982.9) 6954.3,5959.3 ; 6971.03,5976.03 ccw(c7010.87,5936.18) 6954.52,5935.36 cw(c7010.87,5936.18) 6971.03,5976.03 ; 6971.03,5976.03 cw(c6931.18,6015.87) 6930.36,5959.52 ccw(c6931.18,6015.87) 6971.03,5976.03 ; 6971.03,5976.03 7112.21,5976.03 7230,5858.23 ; 7230,5858.23 ccw(c7240.25,5858.23) 7237.23,5848.44 cw(c7240.25,5858.23) 7230,5858.23 ; 7230,5858.23 cw(c7219.75,5858.23) 7222.77,5848.44 ccw(c7219.75,5858.23) 7230,5858.23
OV_D0: P2.1 P5.8 U4.77 | length 2668.2
  Top Layer w10: P5.8@4529.67,6591.26 cw(c4567.93,6582.2) 4558.31,6620.32 ; P5.8@4535,6590 4576.03,6631.03 ; P5.8@4536.26,6584.67 ccw(c4527.2,6622.93) 4565.32,6613.31 ; P2.1@4834.67,7041.26 cw(c4872.93,7032.2) 4863.31,7070.32 ; P2.1@4841.26,7034.67 ccw(c4832.2,7072.93) 4870.32,7063.31 ; U4.77@5840.36,6287.61 5046.94,7081.03 4881.03,7081.03 ; 4559.3,6614.3 ccw(c4582.9,6590.7) 4549.53,6590.21 cw(c4582.9,6590.7) 4559.3,6614.3 ; 4559.3,6614.3 cw(c4535.7,6637.9) 4535.21,6604.53 ccw(c4535.7,6637.9) 4559.3,6614.3 ; 4576.03,6631.03 ccw(c4615.87,6591.18) 4559.52,6590.36 cw(c4615.87,6591.18) 4576.03,6631.03 ; 4576.03,6631.03 cw(c4536.18,6670.87) 4535.36,6614.52 ccw(c4536.18,6670.87) 4576.03,6631.03 ; 4576.03,6631.03 4576.03,6776.03 P2.1@4840,7040 4881.03,7081.03 ; P2.1@4864.3,7064.3 ccw(c4887.9,7040.7) 4854.53,7040.21 cw(c4887.9,7040.7) P2.1@4864.3,7064.3 ; P2.1@4864.3,7064.3 cw(c4840.7,7087.9) 4840.21,7054.53 ccw(c4840.7,7087.9) P2.1@4864.3,7064.3 ; 4881.03,7081.03 ccw(c4920.87,7041.18) 4864.52,7040.36 cw(c4920.87,7041.18) 4881.03,7081.03 ; 4881.03,7081.03 cw(c4841.18,7120.87) 4840.36,7064.52 ccw(c4841.18,7120.87) 4881.03,7081.03
OV_D1: P2.2 P5.9 U4.78 | length 3083
  Top Layer w10: P5.9@4429.67,6491.26 cw(c4467.93,6482.2) 4458.31,6520.32 ; P5.9@4435,6490 4476.03,6531.03 ; P5.9@4436.26,6484.67 ccw(c4427.2,6522.93) 4465.32,6513.31 ; 4909.68,7016.69 cw(c4947.8,7007.07) P2.2@4938.74,7045.33 ; 4916.69,7009.68 ccw(c4907.07,7047.8) P2.2@4945.33,7038.74 ; U4.78@5826.44,6273.69 5060.13,7040 P2.2@4940,7040 4898.97,6998.97 ; 4459.3,6514.3 ccw(c4482.9,6490.7) 4449.53,6490.21 cw(c4482.9,6490.7) 4459.3,6514.3 ; 4459.3,6514.3 cw(c4435.7,6537.9) 4435.21,6504.53 ccw(c4435.7,6537.9) 4459.3,6514.3 ; 4476.03,6531.03 ccw(c4515.87,6491.18) 4459.52,6490.36 cw(c4515.87,6491.18) 4476.03,6531.03 ; 4476.03,6531.03 cw(c4436.18,6570.87) 4435.36,6514.52 ccw(c4436.18,6570.87) 4476.03,6531.03 ; 4476.03,6531.03 4534.05,6531.03 4592.53,6589.51 4592.53,6767.53 4823.97,6998.97 4898.97,6998.97 ; 4898.97,6998.97 ccw(c4859.13,7038.82) 4915.48,7039.64 cw(c4859.13,7038.82) 4898.97,6998.97 ; 4898.97,6998.97 cw(c4938.82,6959.13) 4939.64,7015.48 ccw(c4938.82,6959.13) 4898.97,6998.97 ; 4915.7,7015.7 ccw(c4892.1,7039.3) 4925.47,7039.79 cw(c4892.1,7039.3) 4915.7,7015.7 ; 4915.7,7015.7 cw(c4939.3,6992.1) 4939.79,7025.47 ccw(c4939.3,6992.1) 4915.7,7015.7 ; 4975.07,7040 ccw(c4975.07,7004.93) 4950.27,7029.73 cw(c4975.07,7004.93) 4975.07,7040 ; 4975.07,7040 cw(c4975.07,7075.07) 4950.27,7050.27 ccw(c4975.07,7075.07) 4975.07,7040 ; 4999.21,7040 ccw(c4999.21,6980.79) 4957.34,7022.66 cw(c4999.21,6980.79) 4999.21,7040 ; 4999.21,7040 cw(c4999.21,7099.21) 4957.34,7057.34 ccw(c4999.21,7099.21) 4999.21,7040
OV_D2: P2.3 P5.10 U4.79 | length 2881.2
  Top Layer w10: P5.10@4529.64,6491.1 cw(c4567.3,6483.39) 4557.35,6520.52 ; P5.10@4535,6490 4609.03,6564.03 4609.03,6760 4789.03,6940 ; P5.10@4536.1,6484.64 ccw(c4528.39,6522.3) 4565.52,6512.35 ; P2.3@4834.67,6941.26 cw(c4872.93,6932.2) 4863.31,6970.32 ; P2.3@4841.26,6934.67 ccw(c4832.2,6972.93) 4870.32,6963.31 ; U4.79@5812.52,6259.77 5091.26,6981.03 4881.03,6981.03 ; 4559.8,6514.8 ccw(c4584.6,6490) 4549.53,6490 cw(c4584.6,6490) 4559.8,6514.8 ; 4559.8,6514.8 cw(c4535,6539.6) 4535,6504.53 ccw(c4535,6539.6) 4559.8,6514.8 ; 4576.87,6531.87 ccw(c4618.74,6490) 4559.53,6490 cw(c4618.74,6490) 4576.87,6531.87 ; 4576.87,6531.87 cw(c4535,6573.74) 4535,6514.53 ccw(c4535,6573.74) 4576.87,6531.87 ; 4789.03,6940 ccw(c4789.03,6980.7) 4820.83,6955.3 cw(c4789.03,6980.7) 4789.03,6940 ; 4789.03,6940 cw(c4789.03,6899.3) 4820.83,6924.7 ccw(c4789.03,6899.3) 4789.03,6940 ; 4789.03,6940 P2.3@4840,6940 4881.03,6981.03 ; 4809.81,6940 ccw(c4809.81,6964.1) 4828.65,6949.06 cw(c4809.81,6964.1) 4809.81,6940 ; 4809.81,6940 cw(c4809.81,6915.9) 4828.65,6930.94 ccw(c4809.81,6915.9) 4809.81,6940 ; 4864.3,6964.3 ccw(c4887.9,6940.7) 4854.53,6940.21 cw(c4887.9,6940.7) 4864.3,6964.3 ; 4864.3,6964.3 cw(c4840.7,6987.9) 4840.21,6954.53 ccw(c4840.7,6987.9) 4864.3,6964.3 ; 4881.03,6981.03 ccw(c4920.87,6941.18) 4864.52,6940.36 cw(c4920.87,6941.18) 4881.03,6981.03 ; 4881.03,6981.03 cw(c4841.18,7020.87) 4840.36,6964.52 ccw(c4841.18,7020.87) 4881.03,6981.03
OV_D3: P2.4 P5.11 U4.80 | length 3128.5
  Top Layer w10: P5.11@4429.64,6391.1 cw(c4467.3,6383.39) 4457.35,6420.52 ; P5.11@4435,6390 4493.97,6448.97 4551.99,6448.97 4625.53,6522.51 4625.53,6753.17 4766.18,6893.82 4870.48,6893.82 ; P5.11@4436.1,6384.64 ccw(c4428.39,6422.3) 4465.52,6412.35 ; 4899.09,6911.32 ccw(c4891.16,6978.53) P2.4@4944.3,6936.61 ; 4923.07,6914.15 ccw(c4917.97,6957.38) P2.4@4952.15,6930.42 ; U4.80@5798.6,6245.85 5104.45,6940 P2.4@4940,6940 4916.67,6940 4870.48,6893.82 ; 4459.8,6414.8 ccw(c4484.6,6390) 4449.53,6390 cw(c4484.6,6390) 4459.8,6414.8 ; 4459.8,6414.8 cw(c4435,6439.6) 4435,6404.53 ccw(c4435,6439.6) 4459.8,6414.8 ; 4476.87,6431.87 ccw(c4518.74,6390) 4459.53,6390 cw(c4518.74,6390) 4476.87,6431.87 ; 4476.87,6431.87 cw(c4435,6473.74) 4435,6414.53 ccw(c4435,6473.74) 4476.87,6431.87 ; 4870.49,6893.82 cw(c4925.32,6838.99) 4936.47,6915.73 ccw(c4925.32,6838.99) 4870.49,6893.82 ; 4975.07,6940 ccw(c4975.07,6904.93) 4950.27,6929.73 cw(c4975.07,6904.93) 4975.07,6940 ; 4975.07,6940 cw(c4975.07,6975.07) 4950.27,6950.27 ccw(c4975.07,6975.07) 4975.07,6940 ; 4999.21,6940 ccw(c4999.21,6880.79) 4957.34,6922.66 cw(c4999.21,6880.79) 4999.21,6940 ; 4999.21,6940 cw(c4999.21,6999.21) 4957.34,6957.34 ccw(c4999.21,6999.21) 4999.21,6940 ; 4884.59,6907.92 cw(c4928.9,6863.61) 4937.91,6925.62 ccw(c4928.9,6863.61) 4884.59,6907.92 ; 4898.69,6922.02 cw(c4932.48,6888.23) 4939.35,6935.52 ccw(c4932.48,6888.23) 4898.69,6922.02
OV_D4: P2.5 P5.12 U4.81 | length 2918.4
  Top Layer w10: P5.12@4529.64,6391.1 cw(c4567.3,6383.39) 4557.35,6420.52 ; P5.12@4535,6390 4642.03,6497.03 4642.03,6746.33 4735.7,6840 P2.5@4840,6840 4881.03,6881.03 ; P5.12@4536.1,6384.64 ccw(c4528.39,6422.3) 4565.52,6412.35 ; P2.5@4834.67,6841.26 cw(c4872.93,6832.2) 4863.31,6870.32 ; P2.5@4841.26,6834.67 ccw(c4832.2,6872.93) 4870.32,6863.31 ; U4.81@5784.68,6231.93 5135.59,6881.03 4881.03,6881.03 ; 4559.8,6414.8 ccw(c4584.6,6390) 4549.53,6390 cw(c4584.6,6390) 4559.8,6414.8 ; 4559.8,6414.8 cw(c4535,6439.6) 4535,6404.53 ccw(c4535,6439.6) 4559.8,6414.8 ; 4576.87,6431.87 ccw(c4618.74,6390) 4559.53,6390 cw(c4618.74,6390) 4576.87,6431.87 ; 4576.87,6431.87 cw(c4535,6473.74) 4535,6414.53 ccw(c4535,6473.74) 4576.87,6431.87 ; 4780.79,6840 ccw(c4780.79,6899.21) 4822.66,6857.34 cw(c4780.79,6899.21) 4780.79,6840 ; 4780.79,6840 cw(c4780.79,6780.79) 4822.66,6822.66 ccw(c4780.79,6780.79) 4780.79,6840 ; 4804.93,6840 ccw(c4804.93,6875.07) 4829.73,6850.27 cw(c4804.93,6875.07) 4804.93,6840 ; 4804.93,6840 cw(c4804.93,6804.93) 4829.73,6829.73 ccw(c4804.93,6804.93) 4804.93,6840 ; 4864.3,6864.3 ccw(c4887.9,6840.7) 4854.53,6840.21 cw(c4887.9,6840.7) 4864.3,6864.3 ; 4864.3,6864.3 cw(c4840.7,6887.9) 4840.21,6854.53 ccw(c4840.7,6887.9) 4864.3,6864.3 ; 4881.03,6881.03 ccw(c4920.87,6841.18) 4864.52,6840.36 cw(c4920.87,6841.18) 4881.03,6881.03 ; 4881.03,6881.03 cw(c4841.18,6920.87) 4840.36,6864.52 ccw(c4841.18,6920.87) 4881.03,6881.03
OV_D5: P2.6 P5.13 U4.82 | length 3020.3
  Top Layer w10: P5.13@4429.67,6291.26 cw(c4467.93,6282.2) 4458.31,6320.32 ; P5.13@4435,6290 4476.03,6331.03 ; P5.13@4436.26,6284.67 ccw(c4427.2,6322.93) 4465.32,6313.31 ; 4909.68,6816.69 cw(c4947.8,6807.07) P2.6@4938.74,6845.33 ; 4916.69,6809.68 ccw(c4907.07,6847.8) P2.6@4945.33,6838.74 ; U4.82@5770.77,6218.01 5148.78,6840 P2.6@4940,6840 4898.97,6798.97 ; 4459.3,6314.3 ccw(c4482.9,6290.7) 4449.53,6290.21 cw(c4482.9,6290.7) 4459.3,6314.3 ; 4459.3,6314.3 cw(c4435.7,6337.9) 4435.21,6304.53 ccw(c4435.7,6337.9) 4459.3,6314.3 ; 4476.03,6331.03 ccw(c4515.87,6291.18) 4459.52,6290.36 cw(c4515.87,6291.18) 4476.03,6331.03 ; 4476.03,6331.03 cw(c4436.18,6370.87) 4435.36,6314.52 ccw(c4436.18,6370.87) 4476.03,6331.03 ; 4476.03,6331.03 4534.05,6331.03 4665,6461.98 4665,6730 4733.97,6798.97 4898.97,6798.97 ; 4898.97,6798.97 ccw(c4859.13,6838.82) 4915.48,6839.64 cw(c4859.13,6838.82) 4898.97,6798.97 ; 4898.97,6798.97 cw(c4938.82,6759.13) 4939.64,6815.48 ccw(c4938.82,6759.13) 4898.97,6798.97 ; 4915.7,6815.7 ccw(c4892.1,6839.3) 4925.47,6839.79 cw(c4892.1,6839.3) 4915.7,6815.7 ; 4915.7,6815.7 cw(c4939.3,6792.1) 4939.79,6825.47 ccw(c4939.3,6792.1) 4915.7,6815.7 ; 4975.07,6840 ccw(c4975.07,6804.93) 4950.27,6829.73 cw(c4975.07,6804.93) 4975.07,6840 ; 4975.07,6840 cw(c4975.07,6875.07) 4950.27,6850.27 ccw(c4975.07,6875.07) 4975.07,6840 ; 4999.21,6840 ccw(c4999.21,6780.79) 4957.34,6822.66 cw(c4999.21,6780.79) 4999.21,6840 ; 4999.21,6840 cw(c4999.21,6899.21) 4957.34,6857.34 ccw(c4999.21,6899.21) 4999.21,6840
OV_D6: P2.7 P5.14 U4.85 | length 2861.5
  Top Layer w10: P5.14@4529.64,6291.1 cw(c4567.3,6283.39) 4557.35,6320.52 ; P5.14@4535,6290 4681.5,6436.5 4681.5,6715 4706.5,6740 P2.7@4840,6740 4881.03,6781.03 ; P5.14@4536.1,6284.64 ccw(c4528.39,6322.3) 4565.52,6312.35 ; P2.7@4834.67,6741.26 cw(c4872.93,6732.2) 4863.31,6770.32 ; P2.7@4841.26,6734.67 ccw(c4832.2,6772.93) 4870.32,6763.31 ; U4.85@5729.01,6176.25 5124.23,6781.03 4881.03,6781.03 ; 4559.8,6314.8 ccw(c4584.6,6290) 4549.53,6290 cw(c4584.6,6290) 4559.8,6314.8 ; 4559.8,6314.8 cw(c4535,6339.6) 4535,6304.53 ccw(c4535,6339.6) 4559.8,6314.8 ; 4576.87,6331.87 ccw(c4618.74,6290) 4559.53,6290 cw(c4618.74,6290) 4576.87,6331.87 ; 4576.87,6331.87 cw(c4535,6373.74) 4535,6314.53 ccw(c4535,6373.74) 4576.87,6331.87 ; 4780.79,6740 ccw(c4780.79,6799.21) 4822.66,6757.34 cw(c4780.79,6799.21) 4780.79,6740 ; 4780.79,6740 cw(c4780.79,6680.79) 4822.66,6722.66 ccw(c4780.79,6680.79) 4780.79,6740 ; 4804.93,6740 ccw(c4804.93,6775.07) 4829.73,6750.27 cw(c4804.93,6775.07) 4804.93,6740 ; 4804.93,6740 cw(c4804.93,6704.93) 4829.73,6729.73 ccw(c4804.93,6704.93) 4804.93,6740 ; 4864.3,6764.3 ccw(c4887.9,6740.7) 4854.53,6740.21 cw(c4887.9,6740.7) 4864.3,6764.3 ; 4864.3,6764.3 cw(c4840.7,6787.9) 4840.21,6754.53 ccw(c4840.7,6787.9) 4864.3,6764.3 ; 4881.03,6781.03 ccw(c4920.87,6741.18) 4864.52,6740.36 cw(c4920.87,6741.18) 4881.03,6781.03 ; 4881.03,6781.03 cw(c4841.18,6820.87) 4840.36,6764.52 ccw(c4841.18,6820.87) 4881.03,6781.03
OV_D7: P2.8 P5.15 U4.86 | length 2929.4
  Top Layer w10: P5.15@4429.64,6191.1 cw(c4467.3,6183.39) 4457.35,6220.52 ; P5.15@4435,6190 4493.97,6248.97 4551.99,6248.97 4698,6394.98 4698,6620 4776.97,6698.97 4898.97,6698.97 ; P5.15@4436.1,6184.64 ccw(c4428.39,6222.3) 4465.52,6212.35 ; 4909.68,6716.69 cw(c4947.8,6707.07) P2.8@4938.74,6745.33 ; 4916.69,6709.68 ccw(c4907.07,6747.8) P2.8@4945.33,6738.74 ; U4.86@5715.09,6162.33 5137.42,6740 P2.8@4940,6740 4898.97,6698.97 ; 4459.8,6214.8 ccw(c4484.6,6190) 4449.53,6190 cw(c4484.6,6190) 4459.8,6214.8 ; 4459.8,6214.8 cw(c4435,6239.6) 4435,6204.53 ccw(c4435,6239.6) 4459.8,6214.8 ; 4476.87,6231.87 ccw(c4518.74,6190) 4459.53,6190 cw(c4518.74,6190) 4476.87,6231.87 ; 4476.87,6231.87 cw(c4435,6273.74) 4435,6214.53 ccw(c4435,6273.74) 4476.87,6231.87 ; 4898.97,6698.97 ccw(c4859.13,6738.82) 4915.48,6739.64 cw(c4859.13,6738.82) 4898.97,6698.97 ; 4898.97,6698.97 cw(c4938.82,6659.13) 4939.64,6715.48 ccw(c4938.82,6659.13) 4898.97,6698.97 ; 4915.7,6715.7 ccw(c4892.1,6739.3) 4925.47,6739.79 cw(c4892.1,6739.3) 4915.7,6715.7 ; 4915.7,6715.7 cw(c4939.3,6692.1) 4939.79,6725.47 ccw(c4939.3,6692.1) 4915.7,6715.7 ; 4975.07,6740 ccw(c4975.07,6704.93) 4950.27,6729.73 cw(c4975.07,6704.93) 4975.07,6740 ; 4975.07,6740 cw(c4975.07,6775.07) 4950.27,6750.27 ccw(c4975.07,6775.07) 4975.07,6740 ; 4999.21,6740 ccw(c4999.21,6680.79) 4957.34,6722.66 cw(c4999.21,6680.79) 4999.21,6740 ; 4999.21,6740 cw(c4999.21,6799.21) 4957.34,6757.34 ccw(c4999.21,6799.21) 4999.21,6740
OV_OE: P2.13 P5.7 U4.91 | length 2415.8
  Top Layer w10: P2.13@4834.67,6441.26 cw(c4872.93,6432.2) 4863.31,6470.32 ; P2.13@4840,6440 4881.03,6481.03 ; P2.13@4841.26,6434.67 ccw(c4832.2,6472.93) 4870.32,6463.31 ; U4.91@5645.49,6092.74 5257.2,6481.03 4881.03,6481.03 ; 4864.3,6464.3 ccw(c4887.9,6440.7) 4854.53,6440.21 cw(c4887.9,6440.7) 4864.3,6464.3 ; 4864.3,6464.3 cw(c4840.7,6487.9) 4840.21,6454.53 ccw(c4840.7,6487.9) 4864.3,6464.3 ; 4881.03,6481.03 ccw(c4920.87,6441.18) 4864.52,6440.36 cw(c4920.87,6441.18) 4881.03,6481.03 ; 4881.03,6481.03 cw(c4841.18,6520.87) 4840.36,6464.52 ccw(c4841.18,6520.87) 4881.03,6481.03
  Bottom Layer w10: P5.7@4435,6590 4493.97,6531.03 4748.97,6531.03 P2.13@4840,6440 ; 4459.8,6565.2 ccw(c4435,6540.4) 4435,6575.47 cw(c4435,6540.4) 4459.8,6565.2 ; 4459.8,6565.2 cw(c4484.6,6590) 4449.53,6590 ccw(c4484.6,6590) 4459.8,6565.2 ; 4476.87,6548.13 ccw(c4435,6506.26) 4435,6565.47 cw(c4435,6506.26) 4476.87,6548.13 ; 4476.87,6548.13 cw(c4518.74,6590) 4459.53,6590 ccw(c4518.74,6590) 4476.87,6548.13 ; 4798.13,6481.87 ccw(c4840,6523.74) 4840,6464.53 cw(c4840,6523.74) 4798.13,6481.87 ; 4798.13,6481.87 cw(c4756.26,6440) 4815.47,6440 ccw(c4756.26,6440) 4798.13,6481.87 ; 4815.2,6464.8 ccw(c4840,6489.6) 4840,6454.53 cw(c4840,6489.6) 4815.2,6464.8 ; 4815.2,6464.8 cw(c4790.4,6440) 4825.47,6440 ccw(c4790.4,6440) 4815.2,6464.8
OV_RCLK: P2.14 P5.16 U4.92 | length 2408.6
  Top Layer w10: P5.16@4529.64,6191.1 cw(c4567.3,6183.39) 4557.35,6220.52 ; P5.16@4535,6190 4742.53,6397.53 4897.53,6397.53 P2.14@4940,6440 5270.39,6440 U4.92@5631.57,6078.82 ; P5.16@4536.1,6184.64 ccw(c4528.39,6222.3) 4565.52,6212.35 ; 4909.48,6417.65 cw(c4946.61,6407.7) P2.14@4938.9,6445.36 ; 4917.65,6409.48 ccw(c4907.7,6446.61) P2.14@4945.36,6438.9 ; 4559.8,6214.8 ccw(c4584.6,6190) 4549.53,6190 cw(c4584.6,6190) 4559.8,6214.8 ; 4559.8,6214.8 cw(c4535,6239.6) 4535,6204.53 ccw(c4535,6239.6) 4559.8,6214.8 ; 4576.87,6231.87 ccw(c4618.74,6190) 4559.53,6190 cw(c4618.74,6190) 4576.87,6231.87 ; 4576.87,6231.87 cw(c4535,6273.74) 4535,6214.53 ccw(c4535,6273.74) 4576.87,6231.87 ; 4898.13,6398.13 ccw(c4856.26,6440) 4915.47,6440 cw(c4856.26,6440) 4898.13,6398.13 ; 4898.13,6398.13 cw(c4940,6356.26) 4940,6415.47 ccw(c4940,6356.26) 4898.13,6398.13 ; 4915.2,6415.2 ccw(c4890.4,6440) 4925.47,6440 cw(c4890.4,6440) 4915.2,6415.2 ; 4915.2,6415.2 cw(c4940,6390.4) 4940,6425.47 ccw(c4940,6390.4) 4915.2,6415.2 ; 4975.07,6440 ccw(c4975.07,6404.93) 4950.27,6429.73 cw(c4975.07,6404.93) 4975.07,6440 ; 4975.07,6440 cw(c4975.07,6475.07) 4950.27,6450.27 ccw(c4975.07,6475.07) 4975.07,6440 ; 4999.21,6440 ccw(c4999.21,6380.79) 4957.34,6422.66 cw(c4999.21,6380.79) 4999.21,6440 ; 4999.21,6440 cw(c4999.21,6499.21) 4957.34,6457.34 ccw(c4999.21,6499.21) 4999.21,6440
